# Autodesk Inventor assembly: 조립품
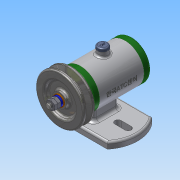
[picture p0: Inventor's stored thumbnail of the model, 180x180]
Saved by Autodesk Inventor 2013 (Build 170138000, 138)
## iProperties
Created: 2017-08
Part Number: 조립품
Document SubType Name: Assembly
Designer: Administrator
Author: Administrator
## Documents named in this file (14)
- C:\Users\Administrator\Desktop\471208V1005\조립품.iam
- C:\Users\Administrator\Desktop\471208V1005\본체.ipt
- C:\Users\Administrator\Desktop\471208V1005\V벨트풀리.ipt
- C:\Users\Administrator\Desktop\471208V1005\고무캡.ipt
- C:\Users\Administrator\Desktop\471208V1005\너트 M 8.ipt
- C:\Users\Administrator\Desktop\471208V1005\뒤커버.ipt
- C:\Users\Administrator\Desktop\471208V1005\베어링 15 x 32 x 9.ipt
- C:\Users\Administrator\Desktop\471208V1005\볼트 M4 x 12.ipt
- C:\Users\Administrator\Desktop\471208V1005\스프링와셔 8.ipt
- C:\Users\Administrator\Desktop\471208V1005\앞커버.ipt
- C:\Users\Administrator\Desktop\471208V1005\오일 실 15 25 7.ipt
- C:\Users\Administrator\Desktop\471208V1005\와셔 8x17.ipt
- C:\Users\Administrator\Desktop\471208V1005\축.ipt
- C:\Users\Administrator\Desktop\471208V1005\키 3 x 3 x 12.ipt
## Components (2 placed, 2 different names)
1. V벨트풀리:1 — 각도:5
2. 고무캡:1 — 각도:9
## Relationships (2: Angle 2)
- 각도:5 [Angle]: V벨트풀리:1
- 각도:9 [Angle]: 고무캡:1
